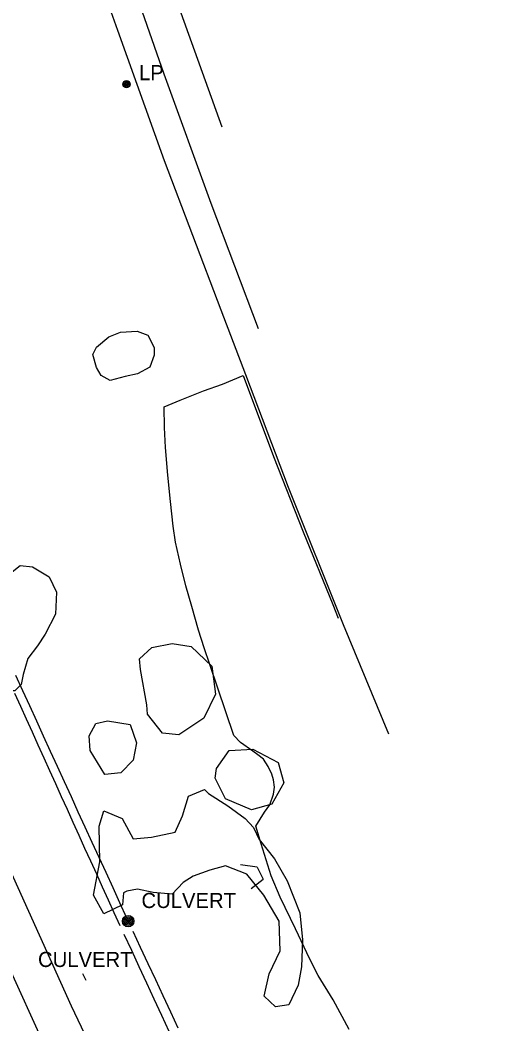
# Model space of a CAD drawing. Extents: x 368532 to 392481, y 10654822 to 10676899.
# Drawn here: x 376060.6 to 376216.7, y 10665749.7 to 10666081.5 of the extents above; entities that cross this region are included whole.
import ezdxf

# ---------------------------------------------------------------- set-up
doc = ezdxf.new("R2010")
doc.units = 0
for name, color, linetype in [('p_Catenary', 7, 'Continuous'), ('p_drainage culvert', 7, 'Continuous'), ('p_dtm slab', 7, 'Continuous'), ('p_railroad rr control', 7, 'Continuous'), ('p_road - paved curb', 7, 'Continuous'), ('p_road paint stripe', 7, 'Continuous'), ('p_utility general pole', 7, 'Continuous'), ('p_veg woods', 7, 'Continuous')]:
    doc.layers.add(name, color=color, linetype=linetype)

msp = doc.modelspace()

# ---------------------------------------------------------------- linework, layer by layer
at = {"layer": 'p_Catenary'}
for points in [[(376059.11, 10665864.92), (376061.4, 10665859.91), (376063.69, 10665854.9), (376065.98, 10665849.89), (376068.27, 10665844.88), (376070.56, 10665839.87), (376072.85, 10665834.86), (376075.14, 10665829.85), (376077.43, 10665824.84), (376079.72, 10665819.83), (376082.01, 10665814.82), (376084.3, 10665809.81), (376086.59, 10665804.81), (376088.89, 10665799.8), (376091.18, 10665794.79), (376093.47, 10665789.78), (376095.76, 10665784.77)], [(376058.79, 10665859.01), (376060.72, 10665854.75), (376062.65, 10665850.48), (376064.58, 10665846.21), (376066.5, 10665841.95), (376068.43, 10665837.68), (376070.36, 10665833.42), (376072.29, 10665829.15), (376074.21, 10665824.88), (376076.14, 10665820.62), (376078.07, 10665816.35), (376080, 10665812.09), (376081.92, 10665807.82), (376083.85, 10665803.55), (376085.78, 10665799.29), (376087.71, 10665795.02), (376089.63, 10665790.76), (376091.56, 10665786.49), (376093.49, 10665782.22)], [(376094.84, 10665779.39), (376097.33, 10665774.03), (376099.81, 10665768.68), (376102.3, 10665763.32), (376104.78, 10665757.96), (376107.27, 10665752.61), (376109.75, 10665747.25)], [(376112.81, 10665748.28), (376110.33, 10665753.61), (376107.85, 10665758.94), (376105.36, 10665764.27), (376102.88, 10665769.6), (376100.4, 10665774.94), (376097.92, 10665780.27)]]:
    msp.add_lwpolyline(points, dxfattribs=at)
at = {"layer": 'p_drainage culvert'}
for p, q in [((376138.86, 10665801.52), (376133.4, 10665802.27)), ((376138.86, 10665801.52), (376140.85, 10665797.51)), ((376136.86, 10665794.42), (376140.85, 10665797.51)), ((376082.41, 10665764.05), (376081.37, 10665766.25))]:
    msp.add_line(p, q, dxfattribs=at)
at = {"layer": 'p_dtm slab'}
for p, q in [((376130.78, 10665962.6), (376134.29, 10665963.97)), ((376134.29, 10665963.97), (376144.3, 10665937.19)), ((376121.17, 10665958.94), (376127.46, 10665961.18)), ((376127.46, 10665961.18), (376130.78, 10665962.6)), ((376113.44, 10665955.85), (376121.17, 10665958.94)), ((376108.13, 10665953.68), (376113.44, 10665955.85)), ((376108.31, 10665946.78), (376108.13, 10665953.68)), ((376108.58, 10665940.18), (376108.31, 10665946.78)), ((376109.42, 10665931.03), (376108.58, 10665940.18)), ((376144.3, 10665937.19), (376154.03, 10665912.38)), ((376110.29, 10665922.39), (376109.42, 10665931.03)), ((376111.14, 10665914.22), (376110.29, 10665922.39)), ((376111.93, 10665908.91), (376111.14, 10665914.22)), ((376154.03, 10665912.38), (376163.81, 10665888.32)), ((376113.52, 10665901.69), (376111.93, 10665908.91)), ((376115.27, 10665894.48), (376113.52, 10665901.69)), ((376117.26, 10665887.69), (376115.27, 10665894.48)), ((376119.46, 10665879.86), (376117.26, 10665887.69)), ((376163.81, 10665888.32), (376165.6, 10665883.8)), ((376121.42, 10665874.01), (376119.46, 10665879.86)), ((376123.29, 10665868.44), (376121.42, 10665874.01)), ((376131.21, 10665844.98), (376123.29, 10665868.44)), ((376133.4, 10665842.68), (376131.21, 10665844.98)), ((376137.38, 10665839.79), (376133.4, 10665842.68)), ((376139.1, 10665838.65), (376137.38, 10665839.79)), ((376140.99, 10665837.24), (376139.1, 10665838.65)), ((376142.53, 10665834.77), (376140.99, 10665837.24)), ((376143.7, 10665832.19), (376142.53, 10665834.77)), ((376144.24, 10665830.36), (376143.7, 10665832.19)), ((376144.57, 10665827.97), (376144.24, 10665830.36)), ((376144.24, 10665825.65), (376144.57, 10665827.97)), ((376143.05, 10665822.11), (376144.24, 10665825.65)), ((376141.26, 10665819.7), (376143.05, 10665822.11)), ((376138.45, 10665815.02), (376141.26, 10665819.7)), ((376140.19, 10665809.27), (376138.45, 10665815.02)), ((376143.52, 10665798.69), (376140.19, 10665809.27)), ((376146.45, 10665791.62), (376143.52, 10665798.69)), ((376151.5, 10665781.07), (376146.45, 10665791.62)), ((376156.21, 10665771.11), (376151.5, 10665781.07)), ((376159.04, 10665765.7), (376156.21, 10665771.11)), ((376163.9, 10665757.71), (376159.04, 10665765.7)), ((376169.19, 10665747.82), (376163.9, 10665757.71))]:
    msp.add_line(p, q, dxfattribs=at)
at = {"layer": 'p_railroad rr control'}
for points in [[(376216.67, 10665483.51), (376197.19, 10665520.27), (376178.65, 10665554.97), (376156.9, 10665596.42), (376137.16, 10665634.25), (376117.31, 10665673.24), (376098.33, 10665711.83), (376077.62, 10665755.55), (376056.45, 10665802.47), (376038.25, 10665845.1), (376032.08, 10665860.05)], [(376018.74, 10665855.38), (376032.08, 10665824.55), (376047.69, 10665788.61), (376067.36, 10665745.41), (376083.96, 10665709.98), (376104.52, 10665668.36), (376124.24, 10665629.54), (376153.01, 10665574.53), (376178.34, 10665526.32), (376202.43, 10665481.04)]]:
    msp.add_lwpolyline(points, dxfattribs=at)
at = {"layer": 'p_road - paved curb'}
for p, q in [((376076.5, 10666124.31), (376092.73, 10666078.11)), ((376092.73, 10666078.11), (376108.2, 10666035.02)), ((376108.2, 10666035.02), (376126.82, 10665985.69)), ((376126.82, 10665985.69), (376135.02, 10665964.3)), ((376135.02, 10665964.3), (376149.04, 10665927.08)), ((376149.04, 10665927.08), (376167.28, 10665881.69)), ((376167.28, 10665881.69), (376182.17, 10665845.58))]:
    msp.add_line(p, q, dxfattribs=at)
at = {"layer": 'p_road paint stripe'}
for p, q in [((376091.07, 10666112.19), (376108.1, 10666063.68)), ((376112.69, 10666086.65), (376127.17, 10666046.13)), ((376108.1, 10666063.68), (376123.6, 10666020.93)), ((376123.6, 10666020.93), (376139.21, 10665979.48))]:
    msp.add_line(p, q, dxfattribs=at)
at = {"layer": 'p_utility general pole'}
for centre, radius in [((376095.74, 10666060.31), 1.19), ((376095.74, 10666060.31), 0.901), ((376095.74, 10666060.31), 0.608), ((376095.74, 10666060.31), 0.337), ((376095.74, 10666060.31), 0.12), ((376096.28, 10665783.66), 1.9), ((376096.28, 10665783.66), 1.44), ((376096.28, 10665783.66), 0.973), ((376096.28, 10665783.66), 0.539), ((376096.28, 10665783.66), 0.192)]:
    msp.add_circle(centre, radius, dxfattribs=at)
at = {"layer": 'p_veg woods'}
for points in [[(376087.4, 10665963.97), (376085.88, 10665966.66), (376084.58, 10665970.89), (376085.79, 10665973.36), (376089.91, 10665976.8), (376093.72, 10665978.33), (376099.23, 10665978.62), (376102.78, 10665977.37), (376104.84, 10665973.23), (376104.82, 10665970.72), (376103.39, 10665966.7), (376099.35, 10665964.55), (376095.26, 10665963.62), (376090.3, 10665962.38)], [(376043.21, 10665886.11), (376046.01, 10665889.47), (376048.89, 10665893.03), (376049.94, 10665894.16), (376054.75, 10665896.59), (376060.62, 10665901.21), (376064.72, 10665900.73), (376070.17, 10665897.43), (376072.58, 10665892.34), (376072.3, 10665885.11), (376068.92, 10665878.48), (376066.36, 10665874.65), (376063.16, 10665870.44), (376061.61, 10665865.15), (376060.99, 10665861.84), (376058.85, 10665859.79), (376053.53, 10665859.79), (376050.18, 10665863.9), (376047.9, 10665867.75), (376046.38, 10665871.88), (376043.1, 10665880.3)], [(376100.39, 10665866.79), (376099.98, 10665870.35), (376104.13, 10665874.13), (376110.82, 10665875.43), (376117.03, 10665874.39), (376123.92, 10665867.88), (376125.13, 10665858.65), (376121.24, 10665850.75), (376112.97, 10665845.21), (376107.65, 10665845.81), (376102.69, 10665852.12), (376102.46, 10665855.14)], [(376083.73, 10665840.04), (376083.45, 10665844.91), (376085.62, 10665848.96), (376089.51, 10665849.84), (376096.93, 10665848.68), (376099.04, 10665842.57), (376097.89, 10665836.89), (376093.81, 10665832.71), (376088.56, 10665832.08)], [(376129.66, 10665840.06), (376137.48, 10665840.5), (376145.8, 10665836.1), (376147.61, 10665829.42), (376143.71, 10665822.34), (376136.94, 10665820.42), (376128.45, 10665824.06), (376125.01, 10665830.94), (376125.42, 10665834.12)], [(376122.75, 10665825.82), (376129.23, 10665821.73), (376134.86, 10665817.6), (376137.65, 10665814.56), (376139.5, 10665810.62), (376144.63, 10665804.3), (376148.72, 10665796.99), (376152.92, 10665786.41), (376153.86, 10665777.54), (376153.55, 10665768.55), (376152.36, 10665762.5), (376149.27, 10665756.04), (376144.95, 10665755.36), (376141.15, 10665758.89), (376142.77, 10665766.21), (376146.49, 10665773.82), (376146.08, 10665783.63), (376141.09, 10665792.29), (376135.5, 10665799.19), (376128.45, 10665802), (376123.21, 10665800.55), (376117.77, 10665798.58), (376114.43, 10665796.44), (376110.8, 10665792.57), (376104.5, 10665793.08), (376099.37, 10665794.21), (376095.81, 10665793.56), (376094.69, 10665793.02), (376094.45, 10665789.1), (376088.21, 10665786.09), (376084.81, 10665792.26), (376086.89, 10665803.25), (376086.69, 10665815.1), (376088.27, 10665820.12), (376094.33, 10665817.64), (376097.96, 10665810.91), (376104.03, 10665811.44), (376111.79, 10665813.07), (376114.2, 10665818.44), (376116.16, 10665824.97), (376121.44, 10665827.14)]]:
    msp.add_lwpolyline(points, close=True, dxfattribs=at)

# ---------------------------------------------------------------- texts
at = {"layer": 'p_drainage culvert'}
for p in [(376098.82, 10665788), (376064.67, 10665768.51)]:
    msp.add_text(' CULVERT', height=5, dxfattribs=at).set_placement(p)
at = {"layer": 'p_utility general pole'}
msp.add_text('LP', height=5, dxfattribs=at).set_placement((376099.86, 10666061.6))

doc.saveas('drawing.dxf')
